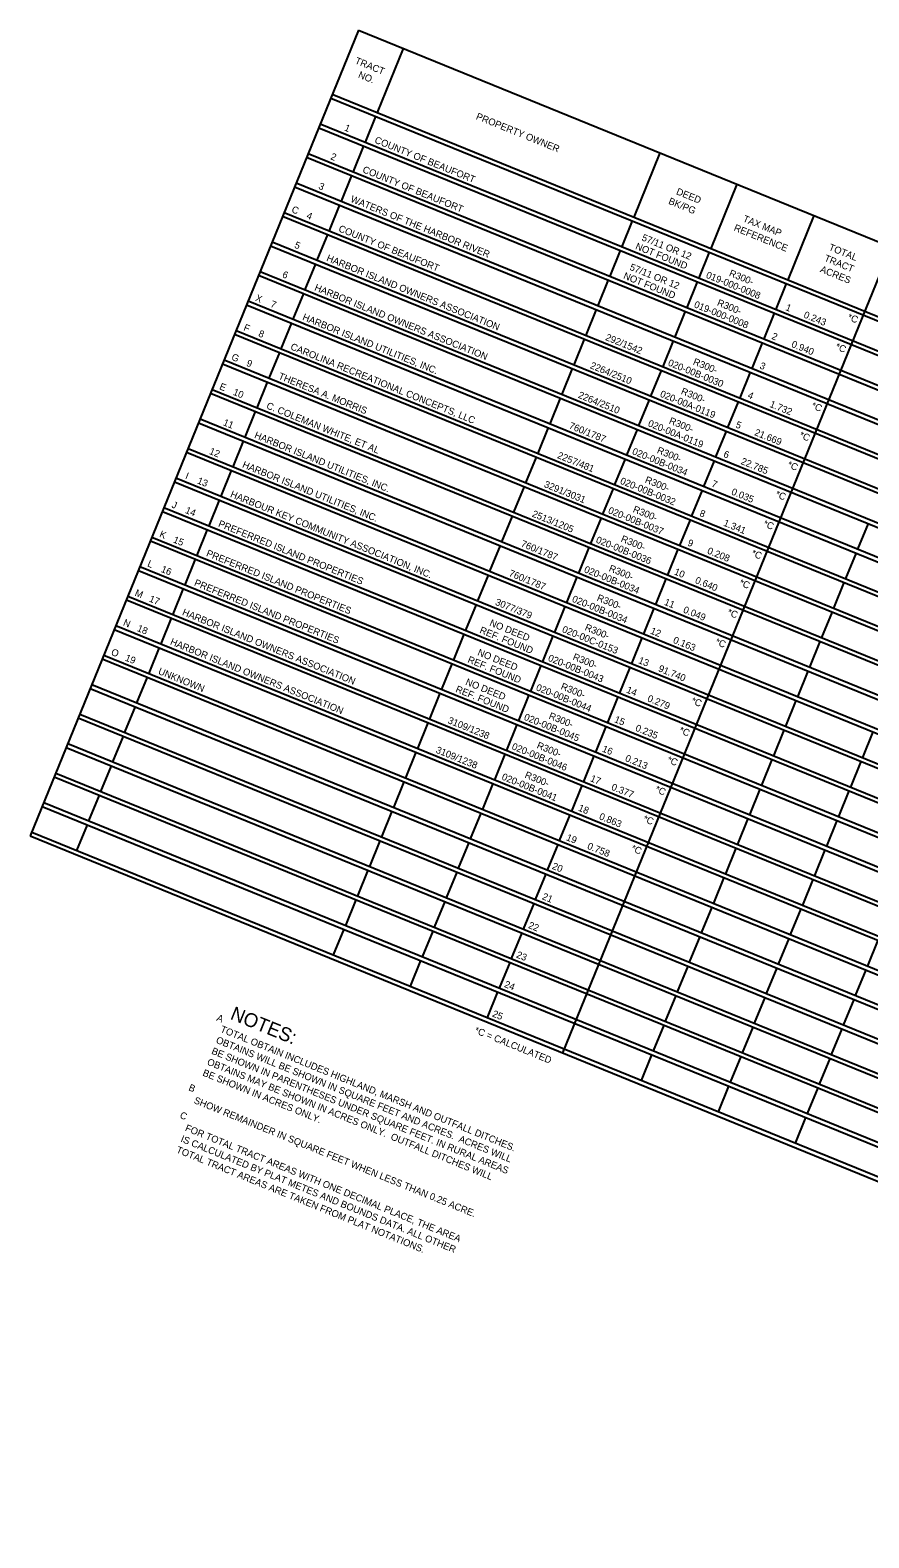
# Model space of a CAD drawing. Extents: x 2163452 to 2324932, y 212763 to 334711.
# Drawn here: x 2163452 to 2163738, y 212854 to 213368 of the extents above; entities that cross this region are included whole.
import ezdxf

# ---------------------------------------------------------------- set-up
doc = ezdxf.new("R2010")
doc.units = 0
for name, color, linetype in [('RD_EX_DV_Prop_txCode', 7, 'Continuous'), ('RD_EX_Misc', 7, 'Continuous'), ('RD_HC_Data_Rel', 7, 'Continuous'), ('RD_SHT_MatchLine', 7, 'Continuous')]:
    doc.layers.add(name, color=color, linetype=linetype)

msp = doc.modelspace()

# ---------------------------------------------------------------- linework, layer by layer
at = {"layer": 'RD_EX_DV_Prop_txCode'}
for p, q in [((2163564.06, 213367.99), (2163452.14, 213093.2)), ((2163564.06, 213367.99), (2164151.66, 213128.65)), ((2163579.37, 213361.75), (2163570.46, 213339.87)), ((2163554.61, 213344.8), (2164142.22, 213105.46)), ((2163555.15, 213346.11), (2164142.75, 213106.78)), ((2163569.89, 213338.57), (2163566.33, 213329.82)), ((2163550.51, 213334.73), (2164138.12, 213095.4)), ((2163551.05, 213336.04), (2164138.65, 213096.71)), ((2163565.79, 213328.51), (2163562.23, 213319.76)), ((2163546.41, 213324.67), (2164134.02, 213085.34)), ((2163546.95, 213325.98), (2164134.55, 213086.65)), ((2163666.88, 213326.11), (2163657.97, 213304.23)), ((2163561.69, 213318.44), (2163558.13, 213309.69)), ((2163542.32, 213314.6), (2164129.92, 213075.27)), ((2163542.85, 213315.92), (2164130.45, 213076.58)), ((2163693.1, 213315.43), (2163684.19, 213293.55)), ((2163557.6, 213308.38), (2163554.03, 213299.63)), ((2163538.22, 213304.54), (2164125.82, 213065.21)), ((2163538.75, 213305.85), (2164126.36, 213066.52)), ((2163657.44, 213302.91), (2163653.87, 213294.16)), ((2163719.36, 213304.73), (2163710.44, 213282.86)), ((2163553.5, 213298.32), (2163549.93, 213289.57)), ((2163534.12, 213294.48), (2164121.72, 213055.14)), ((2163534.65, 213295.79), (2164122.26, 213056.46)), ((2163745.61, 213294.04), (2163633.66, 213019.26)), ((2163653.34, 213292.85), (2163649.77, 213284.1)), ((2163683.66, 213292.24), (2163680.09, 213283.48)), ((2163549.4, 213288.25), (2163545.83, 213279.5)), ((2163530.02, 213284.41), (2164117.62, 213045.08)), ((2163530.55, 213285.73), (2164118.16, 213046.39)), ((2163649.24, 213282.79), (2163645.68, 213274.04)), ((2163679.56, 213282.17), (2163675.99, 213273.42)), ((2163545.3, 213278.19), (2163541.73, 213269.44)), ((2163709.91, 213281.54), (2163706.35, 213272.79)), ((2163525.92, 213274.35), (2164113.52, 213035.02)), ((2163526.45, 213275.66), (2164114.06, 213036.33)), ((2163645.14, 213272.72), (2163641.58, 213263.97)), ((2163675.46, 213272.11), (2163671.89, 213263.36)), ((2163541.2, 213268.13), (2163537.63, 213259.37)), ((2163705.81, 213271.48), (2163702.25, 213262.73)), ((2163521.82, 213264.29), (2164109.42, 213024.95)), ((2163522.35, 213265.6), (2164109.96, 213026.27)), ((2163641.04, 213262.66), (2163637.48, 213253.91)), ((2163671.36, 213262.04), (2163667.8, 213253.29)), ((2163701.71, 213261.41), (2163698.15, 213252.66)), ((2163537.1, 213258.06), (2163533.54, 213249.31)), ((2163517.72, 213254.22), (2164105.33, 213014.89)), ((2163518.26, 213255.53), (2164105.86, 213016.2)), ((2163636.94, 213252.6), (2163633.38, 213243.84)), ((2163667.26, 213251.98), (2163663.7, 213243.23)), ((2163697.61, 213251.35), (2163694.05, 213242.6)), ((2163533, 213248), (2163529.44, 213239.25)), ((2163513.62, 213244.16), (2164101.23, 213004.83)), ((2163514.16, 213245.47), (2164101.76, 213006.14)), ((2163632.84, 213242.53), (2163629.28, 213233.78)), ((2163663.16, 213241.92), (2163659.6, 213233.17)), ((2163693.51, 213241.29), (2163689.95, 213232.54)), ((2163528.9, 213237.93), (2163525.34, 213229.18)), ((2163509.52, 213234.09), (2164097.13, 212994.76)), ((2163510.06, 213235.41), (2164097.66, 212996.07)), ((2163628.75, 213232.47), (2163625.18, 213223.72)), ((2163659.06, 213231.85), (2163655.5, 213223.1)), ((2163689.42, 213231.22), (2163685.85, 213222.47)), ((2163524.8, 213227.87), (2163521.24, 213219.12)), ((2163505.42, 213224.03), (2164093.03, 212984.7)), ((2163505.96, 213225.34), (2164093.56, 212986.01)), ((2163624.65, 213222.4), (2163621.08, 213213.65)), ((2163654.96, 213221.79), (2163651.4, 213213.04)), ((2163685.32, 213221.16), (2163681.75, 213212.41)), ((2163501.86, 213215.28), (2164089.46, 212975.95)), ((2163520.7, 213217.81), (2163517.14, 213209.06)), ((2163501.33, 213213.97), (2164088.93, 212974.63)), ((2163620.55, 213212.34), (2163616.98, 213203.59)), ((2163650.86, 213211.73), (2163647.3, 213202.97)), ((2163681.22, 213211.1), (2163677.65, 213202.34)), ((2163497.76, 213205.22), (2164085.36, 212965.88)), ((2163516.6, 213207.74), (2163513.04, 213198.99)), ((2163497.23, 213203.9), (2164084.83, 212964.57)), ((2163616.45, 213202.28), (2163612.88, 213193.53)), ((2163646.77, 213201.66), (2163643.2, 213192.91)), ((2163677.12, 213201.03), (2163673.55, 213192.28)), ((2163737.82, 213199.77), (2163734.26, 213191.02)), ((2163493.66, 213195.15), (2164081.27, 212955.82)), ((2163512.51, 213197.68), (2163508.94, 213188.93)), ((2163493.13, 213193.84), (2164080.73, 212954.51)), ((2163612.35, 213192.21), (2163608.78, 213183.46)), ((2163642.67, 213191.6), (2163639.1, 213182.85)), ((2163673.02, 213190.97), (2163669.45, 213182.22)), ((2163733.72, 213189.71), (2163730.16, 213180.96)), ((2163489.56, 213185.09), (2164077.17, 212945.76)), ((2163508.41, 213187.62), (2163504.84, 213178.86)), ((2163489.03, 213183.77), (2164076.63, 212944.44)), ((2163608.25, 213182.15), (2163604.69, 213173.4)), ((2163638.57, 213181.53), (2163635, 213172.78)), ((2163668.92, 213180.9), (2163665.36, 213172.15)), ((2163729.62, 213179.65), (2163726.06, 213170.89)), ((2163485.46, 213175.02), (2164073.07, 212935.69)), ((2163504.31, 213177.55), (2163500.74, 213168.8)), ((2163484.93, 213173.71), (2164072.53, 212934.38)), ((2163604.15, 213172.09), (2163600.59, 213163.33)), ((2163634.47, 213171.47), (2163630.9, 213162.72)), ((2163664.82, 213170.84), (2163661.26, 213162.09)), ((2163725.53, 213169.58), (2163721.96, 213160.83)), ((2163481.36, 213164.96), (2164068.97, 212925.63)), ((2163500.21, 213167.49), (2163496.64, 213158.74)), ((2163480.83, 213163.65), (2164068.43, 212924.31)), ((2163600.05, 213162.02), (2163596.49, 213153.27)), ((2163630.37, 213161.41), (2163626.81, 213152.66)), ((2163660.72, 213160.78), (2163657.16, 213152.03)), ((2163721.43, 213159.52), (2163717.86, 213150.77)), ((2163476.73, 213153.58), (2164064.34, 212914.25)), ((2163477.27, 213154.9), (2164064.87, 212915.56)), ((2163496.11, 213157.42), (2163492.55, 213148.67)), ((2163595.95, 213151.96), (2163592.39, 213143.21)), ((2163626.27, 213151.34), (2163622.71, 213142.59)), ((2163656.62, 213150.71), (2163653.06, 213141.96)), ((2163717.33, 213149.45), (2163713.76, 213140.7)), ((2163472.63, 213143.52), (2164060.24, 212904.19)), ((2163473.17, 213144.83), (2164060.77, 212905.5)), ((2163492.01, 213147.36), (2163488.45, 213138.61)), ((2163591.85, 213141.89), (2163588.29, 213133.14)), ((2163622.17, 213141.28), (2163618.61, 213132.53)), ((2163652.52, 213140.65), (2163648.96, 213131.9)), ((2163713.23, 213139.39), (2163709.66, 213130.64)), ((2163468.53, 213133.46), (2164056.14, 212894.12)), ((2163469.07, 213134.77), (2164056.67, 212895.44)), ((2163487.91, 213137.3), (2163484.35, 213128.55)), ((2163587.75, 213131.83), (2163584.19, 213123.08)), ((2163618.07, 213131.21), (2163614.51, 213122.46)), ((2163648.43, 213130.59), (2163644.86, 213121.83)), ((2163709.13, 213129.33), (2163705.57, 213120.58)), ((2163739.48, 213128.7), (2163735.92, 213119.95)), ((2163464.43, 213123.39), (2164052.04, 212884.06)), ((2163464.97, 213124.7), (2164052.57, 212885.37)), ((2163483.81, 213127.23), (2163480.25, 213118.48)), ((2163583.66, 213121.77), (2163580.09, 213113.01)), ((2163613.97, 213121.15), (2163610.41, 213112.4)), ((2163644.33, 213120.52), (2163640.76, 213111.77)), ((2163705.03, 213119.26), (2163701.47, 213110.51)), ((2163735.38, 213118.63), (2163731.82, 213109.88)), ((2163460.33, 213113.33), (2164047.94, 212874)), ((2163460.87, 213114.64), (2164048.47, 212875.31)), ((2163479.71, 213117.17), (2163476.15, 213108.42)), ((2163579.56, 213111.7), (2163575.99, 213102.95)), ((2163609.87, 213111.09), (2163606.31, 213102.34)), ((2163640.23, 213110.46), (2163636.66, 213101.71)), ((2163700.93, 213109.2), (2163697.37, 213100.45)), ((2163731.28, 213108.57), (2163727.72, 213099.82)), ((2163456.24, 213103.26), (2164043.84, 212863.93)), ((2163456.77, 213104.58), (2164044.37, 212865.24)), ((2163475.61, 213107.1), (2163472.05, 213098.35)), ((2163471.52, 213097.04), (2163467.95, 213088.29)), ((2163575.46, 213101.64), (2163571.89, 213092.89)), ((2163605.78, 213101.02), (2163602.21, 213092.27)), ((2163636.13, 213100.39), (2163632.56, 213091.64)), ((2163696.83, 213099.14), (2163693.27, 213090.38)), ((2163727.19, 213098.51), (2163723.62, 213089.76)), ((2163452.14, 213093.2), (2164039.74, 212853.87)), ((2163452.67, 213094.51), (2164040.28, 212855.18)), ((2163571.36, 213091.57), (2163567.79, 213082.82)), ((2163601.68, 213090.96), (2163598.11, 213082.21)), ((2163632.03, 213090.33), (2163628.46, 213081.58)), ((2163692.73, 213089.07), (2163689.17, 213080.32)), ((2163723.09, 213088.44), (2163719.52, 213079.69)), ((2163567.26, 213081.51), (2163563.7, 213072.76)), ((2163597.58, 213080.9), (2163594.01, 213072.14)), ((2163627.93, 213080.27), (2163624.37, 213071.52)), ((2163688.63, 213079.01), (2163685.07, 213070.26)), ((2163718.99, 213078.38), (2163715.42, 213069.63)), ((2163563.16, 213071.45), (2163559.6, 213062.7)), ((2163593.48, 213070.83), (2163589.91, 213062.08)), ((2163623.83, 213070.2), (2163620.27, 213061.45)), ((2163684.54, 213068.94), (2163680.97, 213060.19)), ((2163714.89, 213068.31), (2163711.32, 213059.56)), ((2163559.06, 213061.38), (2163555.5, 213052.63)), ((2163589.38, 213060.77), (2163585.82, 213052.02)), ((2163619.73, 213060.14), (2163616.17, 213051.39)), ((2163680.44, 213058.88), (2163676.87, 213050.13)), ((2163710.79, 213058.25), (2163707.22, 213049.5)), ((2163741.14, 213057.62), (2163737.58, 213048.87)), ((2163585.28, 213050.7), (2163581.72, 213041.95)), ((2163615.63, 213050.08), (2163612.07, 213041.32)), ((2163676.34, 213048.82), (2163672.77, 213040.07)), ((2163706.69, 213048.19), (2163703.13, 213039.44)), ((2163737.04, 213047.56), (2163733.48, 213038.81)), ((2163611.53, 213040.01), (2163607.97, 213031.26)), ((2163672.24, 213038.75), (2163668.67, 213030)), ((2163702.59, 213038.12), (2163699.03, 213029.37)), ((2163732.94, 213037.49), (2163729.38, 213028.74)), ((2163668.14, 213028.69), (2163664.58, 213019.94)), ((2163698.49, 213028.06), (2163694.93, 213019.31)), ((2163728.84, 213027.43), (2163725.28, 213018.68)), ((2163664.04, 213018.63), (2163660.48, 213009.87)), ((2163694.39, 213018), (2163690.83, 213009.24)), ((2163724.75, 213017.37), (2163721.18, 213008.62)), ((2163690.29, 213007.93), (2163686.73, 212999.18)), ((2163720.65, 213007.3), (2163717.08, 212998.55)), ((2163716.55, 212997.24), (2163712.98, 212988.49))]:
    msp.add_line(p, q, dxfattribs=at)

# ---------------------------------------------------------------- texts
at = {"layer": 'RD_EX_Misc'}
for s, height, p in [('1', 2.36, (2163559.06, 213333.84)), ('COUNTY OF BEAUFORT', 2.3623, (2163569.36, 213329.65)), ('2', 2.36, (2163554.34, 213324.03)), ('COUNTY OF BEAUFORT', 2.3623, (2163565.26, 213319.58)), ('3', 2.36, (2163550.24, 213313.97)), ('WATERS OF THE HARBOR RIVER', 2.3623, (2163561.16, 213309.52)), ('4', 2.36, (2163546.14, 213303.9)), ('COUNTY OF BEAUFORT', 2.3623, (2163557.06, 213299.46)), ('57/11 OR 12', 2.3623, (2163660.44, 213296.38)), ('5', 2.36, (2163542.04, 213293.84)), ('NOT FOUND', 2.362, (2163658.29, 213293.42)), ('HARBOR ISLAND OWNERS ASSOCIATION', 2.3623, (2163552.96, 213289.39)), ('57/11 OR 12', 2.3623, (2163656.34, 213286.31)), ('6', 2.36, (2163537.89, 213283.8)), ('NOT FOUND', 2.362, (2163654.19, 213283.36)), ('019-000-0008', 2.3623, (2163682.36, 213283.62)), ('R300-', 2.362, (2163690.24, 213284.24)), ('HARBOR ISLAND OWNERS ASSOCIATION', 2.3623, (2163548.86, 213279.33)), ('7', 2.36, (2163533.84, 213273.71)), ('019-000-0008', 2.3623, (2163678.26, 213273.56)), ('R300-', 2.362, (2163686.14, 213274.17)), ('0.243', 2.362, (2163715.66, 213270.06)), ('HARBOR ISLAND UTILITIES, INC.', 2.3623, (2163544.77, 213269.26)), ('*C', 2.362, (2163730.58, 213269.3)), ('8', 2.36, (2163529.75, 213263.65)), ('292/1542', 2.362, (2163648.08, 213262.38)), ('0.940', 2.362, (2163711.47, 213260.03)), ('CAROLINA RECREATIONAL CONCEPTS, LLC', 2.3623, (2163540.67, 213259.2)), ('*C', 2.362, (2163726.48, 213259.23)), ('9', 2.36, (2163525.65, 213253.58)), ('THERESA A. MORRIS', 2.3623, (2163536.57, 213249.14)), ('2264/2510', 2.362, (2163642.86, 213252.78)), ('020-00B-0030', 2.3623, (2163669.39, 213253.7)), ('R300-', 2.362, (2163677.94, 213254.05)), ('R300-', 2.362, (2163673.84, 213243.98)), ('10', 2.362, (2163521.1, 213243.7)), ('C. COLEMAN WHITE, ET AL', 2.3623, (2163532.47, 213239.07)), ('2264/2510', 2.362, (2163638.76, 213242.71)), ('020-00A-0119', 2.3623, (2163666.67, 213243.08)), ('1.732', 2.362, (2163704.06, 213239.58)), ('*C', 2.362, (2163718.28, 213239.11)), ('R300-', 2.362, (2163669.75, 213233.92)), ('11', 2.362, (2163517.71, 213233.35)), ('HARBOR ISLAND UTILITIES, INC.', 2.3623, (2163528.37, 213229.01)), ('760/1787', 2.362, (2163635.64, 213232.25)), ('020-00A-0119', 2.3623, (2163662.57, 213233.02)), ('21.669', 2.362, (2163698.88, 213229.96)), ('*C', 2.362, (2163714.18, 213229.04)), ('12', 2.362, (2163512.99, 213223.54)), ('020-00B-0034', 2.3623, (2163657.18, 213223.48)), ('R300-', 2.362, (2163665.65, 213223.86)), ('HARBOR ISLAND UTILITIES, INC.', 2.3623, (2163524.27, 213218.95)), ('2257/481', 2.362, (2163631.68, 213222.13)), ('22.785', 2.362, (2163694.26, 213220.11)), ('*C', 2.362, (2163710.08, 213218.98)), ('13', 2.362, (2163508.89, 213213.48)), ('020-00B-0032', 2.3623, (2163653.08, 213213.41)), ('R300-', 2.362, (2163661.55, 213213.79)), ('HARBOUR KEY COMMUNITY ASSOCIATION, INC.', 2.3623, (2163520.17, 213208.88)), ('3291/3031', 2.362, (2163627.14, 213212.25)), ('0.035', 2.362, (2163690.98, 213209.71)), ('*C', 2.362, (2163705.98, 213208.91)), ('14', 2.362, (2163504.79, 213203.41)), ('020-00B-0037', 2.3623, (2163648.98, 213203.35)), ('R300-', 2.362, (2163657.45, 213203.73)), ('PREFERRED ISLAND PROPERTIES', 2.3623, (2163516.07, 213198.82)), ('2513/1205', 2.362, (2163623.04, 213202.18)), ('1.341', 2.362, (2163688.29, 213199.07)), ('*C', 2.362, (2163701.88, 213198.85)), ('15', 2.362, (2163500.69, 213193.35)), ('020-00B-0036', 2.3623, (2163644.83, 213193.31)), ('R300-', 2.362, (2163653.35, 213193.66)), ('PREFERRED ISLAND PROPERTIES', 2.3623, (2163511.97, 213188.75)), ('760/1787', 2.362, (2163619.25, 213191.99)), ('0.208', 2.362, (2163682.78, 213189.58)), ('*C', 2.362, (2163697.79, 213188.79)), ('16', 2.362, (2163496.54, 213183.31)), ('020-00B-0034', 2.3623, (2163640.78, 213183.22)), ('R300-', 2.362, (2163649.25, 213183.6)), ('PREFERRED ISLAND PROPERTIES', 2.3623, (2163507.87, 213178.69)), ('760/1787', 2.362, (2163615.15, 213181.93)), ('0.640', 2.362, (2163678.63, 213179.54)), ('*C', 2.362, (2163693.69, 213178.72)), ('17', 2.362, (2163492.49, 213173.22)), ('3077/379', 2.362, (2163610.48, 213172.1)), ('020-00B-0034', 2.3623, (2163636.68, 213173.16)), ('R300-', 2.362, (2163645.15, 213173.54)), ('HARBOR ISLAND OWNERS ASSOCIATION', 2.3623, (2163503.78, 213168.63)), ('0.049', 2.362, (2163674.58, 213169.46)), ('*C', 2.362, (2163689.59, 213168.66)), ('18', 2.362, (2163488.39, 213163.16)), ('REF. FOUND', 2.362, (2163605.18, 213162.52)), ('NO DEED', 2.362, (2163608.55, 213164.98)), ('020-00C-0153', 2.3623, (2163633.29, 213162.81)), ('R300-', 2.362, (2163641.05, 213163.47)), ('HARBOR ISLAND OWNERS ASSOCIATION', 2.3623, (2163499.68, 213158.56)), ('0.163', 2.362, (2163671.13, 213159.13)), ('*C', 2.362, (2163685.49, 213158.59)), ('19', 2.362, (2163484.29, 213153.09)), ('REF. FOUND', 2.362, (2163601.08, 213152.46)), ('NO DEED', 2.362, (2163604.45, 213154.91)), ('020-00B-0043', 2.3623, (2163628.49, 213153.03)), ('R300-', 2.362, (2163636.95, 213153.41)), ('UNKNOWN', 2.362, (2163495.58, 213148.5)), ('91.740', 2.362, (2163666.11, 213149.44)), ('REF. FOUND', 2.362, (2163596.98, 213142.4)), ('NO DEED', 2.362, (2163600.35, 213144.85)), ('020-00B-0044', 2.3623, (2163624.39, 213142.97)), ('R300-', 2.362, (2163632.85, 213143.34)), ('0.279', 2.362, (2163662.37, 213139.23)), ('*C', 2.362, (2163677.29, 213138.47)), ('3109/1238', 2.362, (2163594.34, 213131.74)), ('020-00B-0045', 2.3623, (2163620.29, 213132.9)), ('R300-', 2.362, (2163628.76, 213133.28)), ('0.235', 2.362, (2163658.27, 213129.17)), ('*C', 2.362, (2163673.19, 213128.4)), ('3109/1238', 2.362, (2163590.25, 213121.67)), ('020-00B-0046', 2.3623, (2163616.14, 213122.86)), ('R300-', 2.362, (2163624.66, 213123.22)), ('0.213', 2.362, (2163654.79, 213118.85)), ('*C', 2.362, (2163669.09, 213118.34)), ('020-00B-0041', 2.3623, (2163612.71, 213112.52)), ('R300-', 2.362, (2163620.56, 213113.15)), ('0.377', 2.362, (2163650.07, 213109.04)), ('*C', 2.362, (2163664.99, 213108.28)), ('0.863', 2.362, (2163645.92, 213099)), ('*C', 2.362, (2163660.89, 213098.21)), ('0.758', 2.362, (2163641.87, 213088.91)), ('*C', 2.362, (2163656.8, 213088.15)), ('*C = CALCULATED', 2.3623, (2163603.41, 213026.07))]:
    msp.add_text(s, height=height, rotation=337.8388, dxfattribs=at).set_placement(p)
at = {"layer": 'RD_HC_Data_Rel'}
for s, height, p in [('C', 2.36, (2163541.04, 213305.98)), ('X', 2.36, (2163528.72, 213275.8)), ('1', 2.36, (2163709.46, 213272.58)), ('F', 2.36, (2163524.69, 213265.71)), ('2', 2.36, (2163704.74, 213262.77)), ('G', 2.36, (2163520.54, 213255.66)), ('3', 2.36, (2163700.65, 213252.71)), ('E', 2.36, (2163516.45, 213245.6)), ('4', 2.36, (2163696.55, 213242.64)), ('5', 2.36, (2163692.45, 213232.58)), ('6', 2.36, (2163688.3, 213222.54)), ('I', 2.36, (2163504.82, 213215.13)), ('7', 2.36, (2163684.25, 213212.45)), ('J', 2.36, (2163500.19, 213205.29)), ('8', 2.36, (2163680.15, 213202.39)), ('K', 2.36, (2163496, 213195.26)), ('9', 2.36, (2163676.05, 213192.32)), ('L', 2.36, (2163491.9, 213185.2)), ('10', 2.362, (2163671.5, 213182.44)), ('M', 2.36, (2163487.61, 213175.21)), ('11', 2.362, (2163668.11, 213172.09)), ('N', 2.36, (2163483.65, 213165.09)), ('12', 2.362, (2163663.39, 213162.28)), ('O', 2.36, (2163479.52, 213155.04)), ('13', 2.362, (2163659.29, 213152.22)), ('14', 2.362, (2163655.2, 213142.15)), ('15', 2.362, (2163651.1, 213132.09)), ('16', 2.362, (2163646.95, 213122.05)), ('17', 2.362, (2163642.9, 213111.96)), ('18', 2.362, (2163638.8, 213101.9)), ('19', 2.362, (2163634.7, 213091.83)), ('20', 2.362, (2163629.89, 213082.06)), ('21', 2.362, (2163626.5, 213071.71)), ('22', 2.362, (2163621.78, 213061.89)), ('23', 2.362, (2163617.68, 213051.83)), ('24', 2.362, (2163613.58, 213041.77)), ('25', 2.362, (2163609.49, 213031.7))]:
    msp.add_text(s, height=height, rotation=337.8388, dxfattribs=at).set_placement(p)
at = {"layer": 'RD_SHT_MatchLine'}
for s, height, p in [('TRACT', 2.362, (2163562.66, 213356.69)), ('NO.', 2.362, (2163563.78, 213351.9)), ('PROPERTY OWNER', 2.3623, (2163603.95, 213337.71)), ('DEED', 2.362, (2163672.2, 213312.08)), ('BK/PG', 2.362, (2163669.56, 213308.82)), ('TAX MAP', 2.362, (2163694.95, 213302.81)), ('REFERENCE', 2.362, (2163691.86, 213299.73)), ('TOTAL', 2.362, (2163724.2, 213293.07)), ('ACRES', 2.362, (2163721.28, 213285.59)), ('TRACT', 2.362, (2163722.67, 213289.35)), ('A', 2.36, (2163515.48, 213030.34)), ('NOTES:', 4.725, (2163520.06, 213030.87)), ('TOTAL OBTAIN INCLUDES HIGHLAND, MARSH AND OUTFALL DITCHES.', 2.3623, (2163516.79, 213026.45)), ('BE SHOWN IN PARENTHESES UNDER SQUARE FEET. IN RURAL AREAS', 2.3623, (2163513.76, 213019.01)), ('OBTAINS WILL BE SHOWN IN SQUARE FEET AND ACRES.  ACRES WILL', 2.3623, (2163515.28, 213022.73)), ('OBTAINS MAY BE SHOWN IN ACRES ONLY.  OUTFALL DITCHES WILL', 2.3623, (2163512.25, 213015.29)), ('BE SHOWN IN ACRES ONLY.', 2.3623, (2163510.73, 213011.57)), ('B', 2.36, (2163505.94, 213006.55)), ('SHOW REMAINDER IN SQUARE FEET WHEN LESS THAN 0.25 ACRE.', 2.3623, (2163507.75, 213002.17)), ('C', 2.36, (2163502.95, 212997.14)), ('FOR TOTAL TRACT AREAS WITH ONE DECIMAL PLACE, THE AREA', 2.3623, (2163504.77, 212992.76)), ('IS CALCULATED BY PLAT METES AND BOUNDS DATA. ALL OTHER', 2.3623, (2163503.26, 212989.04)), ('TOTAL TRACT AREAS ARE TAKEN FROM PLAT NOTATIONS.', 2.3623, (2163501.74, 212985.32))]:
    msp.add_text(s, height=height, rotation=337.8388, dxfattribs=at).set_placement(p)

doc.saveas('drawing.dxf')
